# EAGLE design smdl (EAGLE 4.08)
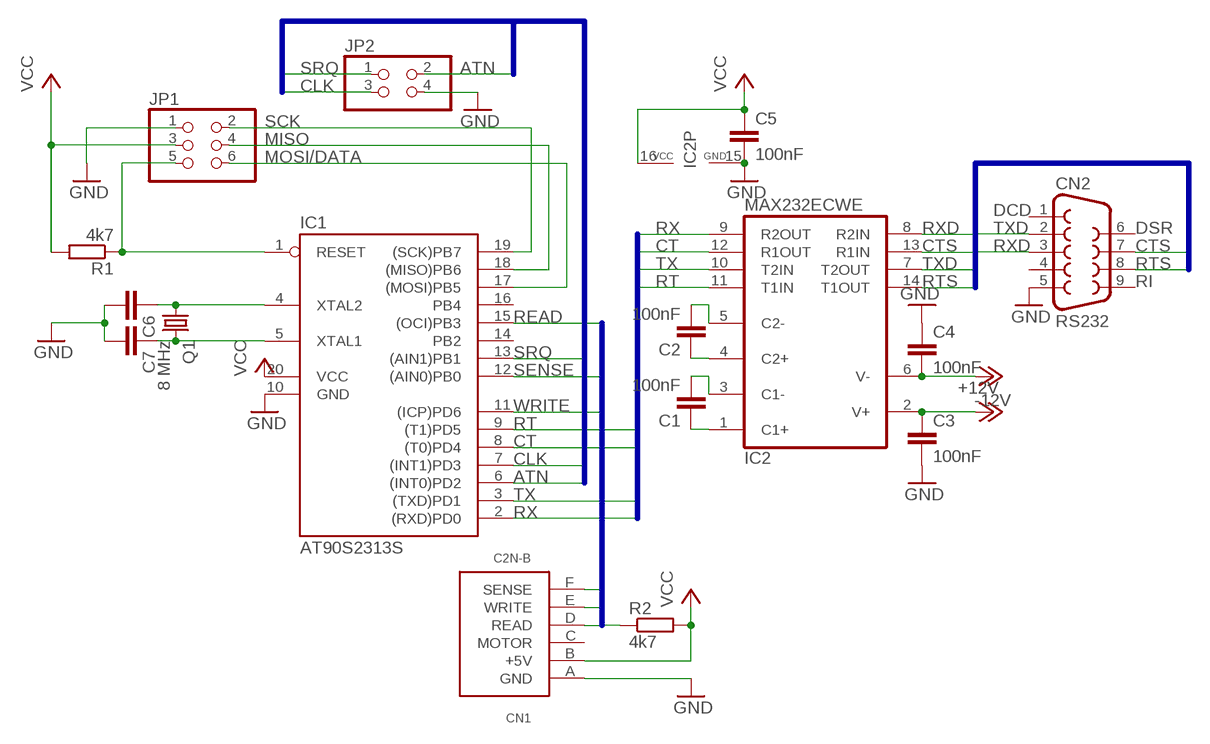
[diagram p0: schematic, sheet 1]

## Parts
C1  100nF  C-EUC0805  [C0805]
C2  100nF  C-EUC0805  [C0805]
C3  100nF  C-EUC0805  [C0805]
C4  100nF  C-EUC0805  [C0805]
C5  100nF  C-EUC0805  [C0805]
C6  C-EUC0603  [C0603]
C7  C-EUC0603  [C0603]
CN1  C2N-B  [C2N-B]
CN2  RS232  F09D  [F09D]
IC1  AT90S2313S  [SO-20L]
IC2  MAX232ECWE  [SO16L]
JP1  PINHD-2X3  [2X03]
JP2  PINHD-2X2  [2X02]
Q1  8 MHz  SM49  [SM49]
R1  4k7  R-EU_R0805  [R0805]
R2  4k7  R-EU_R0805  [R0805]

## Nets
+12V: C3.2 IC2.2(V+)
-12V: C4.1 IC2.6(V-)
ATN: IC1.6((INT0)PD2) JP2.2
C1+: C1.2 IC2.1(C1+)
C1-: C1.1 IC2.3(C1-)
C2+: C2.2 IC2.4(C2+)
C2-: C2.1 IC2.5(C2-)
CLK: IC1.7((INT1)PD3) JP2.3
CT: IC1.8((T0)PD4) IC2.12(R1OUT)
CTS: CN2.7 IC2.13(R1IN)
GND: C3.1 C4.2 C5.1 C6.1 C7.1 CN1.A(GND) CN2.5 IC1.10(GND) IC2.15(GND) JP1.1 JP2.4
MISO: IC1.18((MISO)PB6) JP1.4
MOSI/DATA: IC1.17((MOSI)PB5) JP1.6
READ: CN1.D(READ) IC1.15((OCI)PB3) R2.1
RESET: IC1.1(RESET) JP1.5 R1.1
RT: IC1.9((T1)PD5) IC2.11(T1IN)
RTS: CN2.8 IC2.14(T1OUT)
RX: IC1.2((RXD)PD0) IC2.9(R2OUT)
RXD: CN2.3 IC2.8(R2IN)
SCK: IC1.19((SCK)PB7) JP1.2
SENSE: CN1.F(SENSE) IC1.12((AIN0)PB0)
SRQ: IC1.13((AIN1)PB1) JP2.1
TX: IC1.3((TXD)PD1) IC2.10(T2IN)
TXD: CN2.2 IC2.7(T2OUT)
VCC: C5.2 CN1.B(+5V) IC1.20(VCC) IC2.16(VCC) JP1.3 R1.2 R2.2
WRITE: CN1.E(WRITE) IC1.11((ICP)PD6)
XTAL1: C7.2 IC1.5(XTAL1) Q1.2
XTAL2: C6.2 IC1.4(XTAL2) Q1.1
Unconnected: CN1.C(MOTOR) CN2.1 CN2.4 CN2.6 CN2.9 IC1.14(PB2) IC1.16(PB4)

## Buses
WRITE,READ,SENSE,MOTOR
DTR,CTS,RTS,RXD,TXD,DSR,RI,DCD
RX,TX,CT,RT
ATN,CLK,DATA,SRQ

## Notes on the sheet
- DCD
- DSR
- RI

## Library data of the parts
C1-C7 = rcl:C-EU: CAPACITOR, European symbol
CN1 = vic-20:C2N: Datassette connector
CN2 = con-subd:F09D: HARTING SUB-D
IC1 = atmel:AT90S2313: MICROCONTROLLER 2 Kbytes FLASH 128 bytes SRAM 128 bytes EEPROM UART
IC2 = maxim:MAX232ECWE: RS232 TRANSEIVER
JP1 = pinhead:PINHD-2X3: PIN HEADER
JP2 = pinhead:PINHD-2X2: PIN HEADER
Q1 = crystal:SM49: CRYSTAL
R1 R2 = rcl:R-EU_: RESISTOR, European symbol

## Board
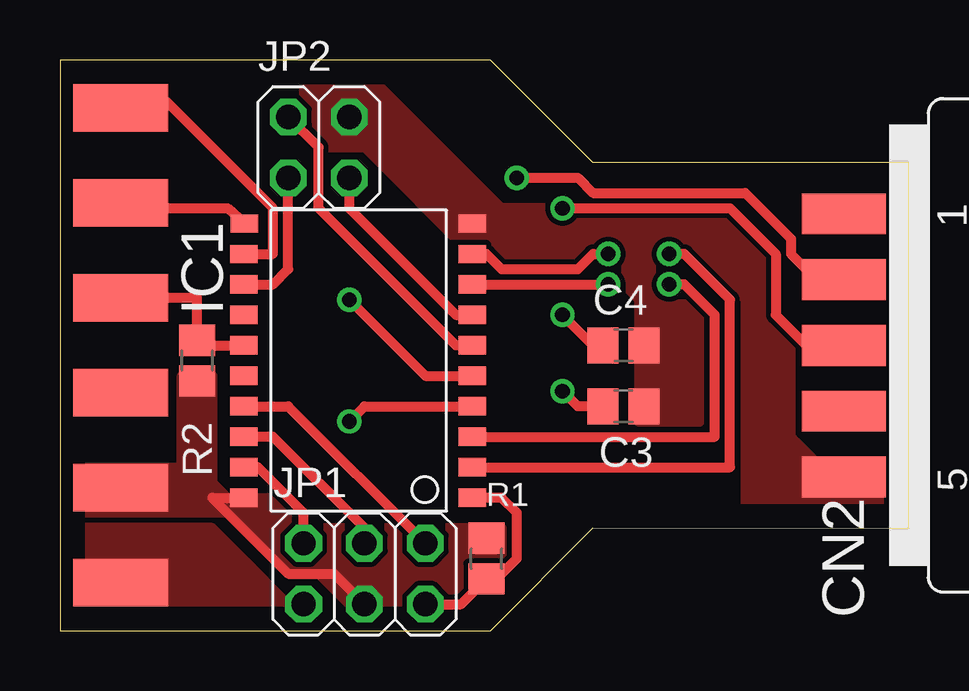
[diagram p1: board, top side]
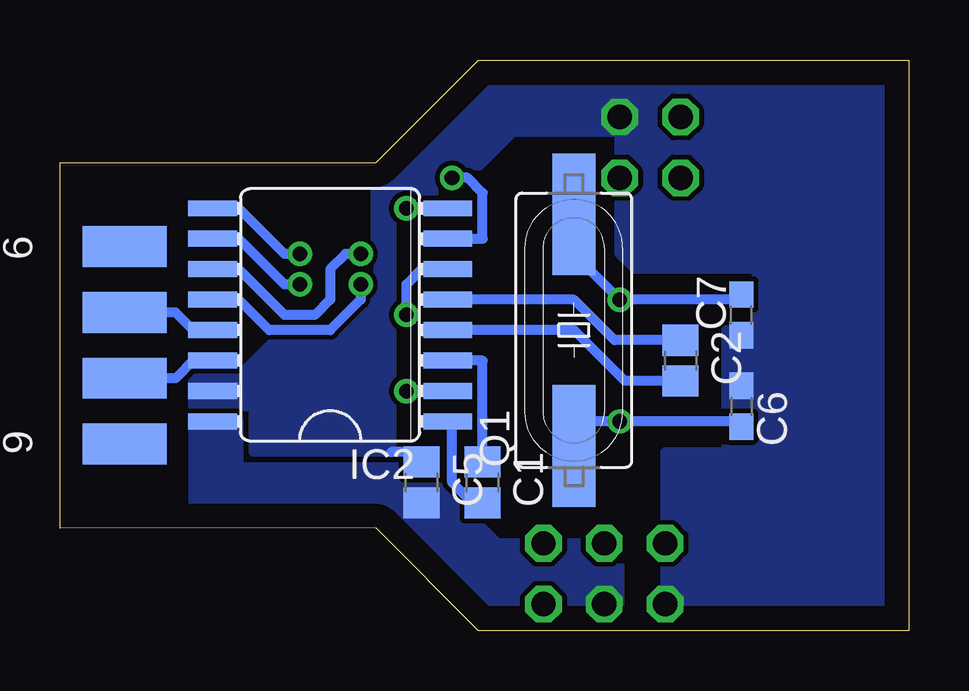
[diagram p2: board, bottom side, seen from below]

Size 35.39 x 23.8 mm. Coordinates in mm from the lower left corner, seen from the top.
Outline: 0,23.8 0,0 17.94,0 22.22,4.28 35.39,4.28 35.39,19.53 34.92,19.53 34.92,19.52 22.22,19.52 17.94,23.8 0,23.8
Copper layers used: Top, Bottom

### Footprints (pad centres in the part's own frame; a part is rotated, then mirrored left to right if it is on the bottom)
C0805 = smd 1.3 x 1.5: 1 -0.85,0; 2 0.85,0
C0603 = smd 1.1 x 1: 1 -0.85,0; 2 0.85,0
C2N-B = smd 1.98 x 3.96 bottom: A -9.9,0; B -5.94,0; C -1.98,0; D 1.98,0; E 5.94,0; F 9.9,0
F09D = smd 1.7 x 3.5: 1 -5.486,-6.045; 2 -2.743,-6.045; 3 0,-6.045; 4 2.743,-6.045; 5 5.486,-6.045 | smd 1.7 x 3.5 bottom: 6 -4.115,-6.045; 7 -1.372,-6.045; 8 1.372,-6.045; 9 4.115,-6.045
SO-20L = smd 0.762 x 1.143: 1 -5.08,-5.131; 2 -3.81,-5.131; 3 -2.54,-5.131; 4 -1.27,-5.131; 5 0,-5.131; 6 1.27,-5.131; 7 2.54,-5.131; 8 3.81,-5.131; 9 5.08,-5.131; 10 6.35,-5.131; 11 6.35,4.369; 12 5.08,4.394; 13 3.81,4.394; 14 2.54,4.394; 15 1.27,4.394; 16 0,4.394; 17 -1.27,4.394; 18 -2.54,4.394; 19 -3.81,4.394; 20 -5.08,4.394
SO16L = smd 0.66 x 2.032: 1 -4.445,-4.902; 2 -3.175,-4.902; 3 -1.905,-4.902; 4 -0.635,-4.902; 5 0.635,-4.902; 6 1.905,-4.902; 7 3.175,-4.902; 8 4.445,-4.902; 9 4.445,4.902; 10 3.175,4.902; 11 1.905,4.902; 12 0.635,4.902; 13 -0.635,4.902; 14 -1.905,4.902; 15 -3.175,4.902; 16 -4.445,4.902
2X03 = drill 1.016 octagon: 1 -2.54,-1.27; 2 -2.54,1.27; 3 0,-1.27; 4 0,1.27; 5 2.54,-1.27; 6 2.54,1.27
2X02 = drill 1.016 octagon: 1 -1.27,-1.27; 2 -1.27,1.27; 3 1.27,-1.27; 4 1.27,1.27
SM49 = smd 5.08 x 1.778: 1 -4.826,0; 2 4.826,0
R0805 = smd 1.3 x 1.5: 1 -0.85,0; 2 0.85,0

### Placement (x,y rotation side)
C1  17.78,6.18 270 bottom
C2  9.52,11.27 270 bottom
C3  23.49,9.36 180 top
C4  23.49,11.9 0 top
C5  20.32,6.18 270 bottom
C6  6.98,9.36 270 bottom
C7  6.98,13.17 90 bottom
CN1  2.54,11.9 90 bottom
CN2  38.73,11.9 270 top
IC1  12.06,10.63 90 top
IC2  24.12,13.17 90 bottom
JP1  12.69,2.38 0 top
JP2  10.79,20.16 0 top
Q1  13.96,12.54 90 bottom
R1  17.78,3.01 90 top
R2  5.71,11.27 270 top

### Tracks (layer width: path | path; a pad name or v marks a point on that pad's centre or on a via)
+12V  (via drill 0.61 pad 0.61)
  Top 0.406: v20.95,10 21.59,9.36 C3.2
  Bottom 0.406: v20.95,10 IC2.2
-12V  (via drill 0.61 pad 0.61)
  Top 0.406: C4.1 22.22,11.9 v20.95,13.17
  Bottom 0.406: IC2.6 20.32,15.08 20.95,14.44 v20.95,13.17
ATN
  Top 0.406: IC1.6 16.51,11.9 10.79,17.62 10.79,20.16 JP2.2
C1+
  Bottom 0.406: C1.2 18.2,5.33 19.05,6.18 19.05,8.73 IC2.1
C1-
  Bottom 0.406: C1.1 17.78,11.27 IC2.3
C2+
  Bottom 0.406: C2.2 11.84,10.42 13.96,12.54 IC2.4
C2-
  Bottom 0.406: C2.1 12.27,12.12 13.96,13.81 IC2.5
CLK
  Top 0.406: IC1.7 16.51,13.17 12.06,17.62 JP2.3
CT  (via drill 0.61 pad 0.61)
  Top 0.406: IC1.8 v22.86,14.44
  Bottom 0.406: v22.86,14.44 22.86,13.81 24.12,12.54 26.67,12.54 27.94,13.81 IC2.12
CTS
  Bottom 0.406: IC2.13 29.84,12.54 30.58,13.27 CN2.7
GND
  Bottom 0.406: C5.1 20.32,7.46 21.59,7.46
  pour Bottom (no thermals): -0.01,-0.17 10.15,-0.17 10.15,7.46 7.62,7.46 7.62,12.54 6.34,12.54 6.34,15.08 11.42,15.08 12.06,15.71 12.06,20.79 20.95,20.79 17.78,23.96 -0.01,23.96
  pour Top (no thermals): 24.12,8.73 26.67,8.73 26.67,13.17 25.39,14.44 25.39,16.35 26.03,16.35 28.57,13.81 28.57,4.28 34.28,4.28 34.28,6.82 31.75,6.82 30.48,8.09 30.48,11.9 29.84,12.54 29.84,15.08 27.3,17.62 24.12,17.62
  pour Top (no thermals): 24.12,17.62 18.41,17.62 12.69,23.33 10.15,23.33 10.15,20.16 12.69,20.16 17.14,15.71 22.22,15.71 24.12,13.81
  pour Bottom (no thermals): 27.3,7.46 27.3,9.36 29.84,9.36 29.84,10.63 27.94,10.63 22.22,16.35 22.22,19.52 18.41,23.33 16.51,23.33 16.51,20.79 19.05,18.25 20.95,18.25 21.59,17.62 21.59,7.46
  pour Top (no thermals): 10.79,-0.17 6.34,4.28 -0.01,4.28 -0.01,-0.17
MISO
  Top 0.406: IC1.18 8.88,8.09 12.69,4.28 JP1.4
MOSI/DATA
  Top 0.406: IC1.17 9.52,9.36 JP1.6
READ
  Top 0.406: 5.71,11.9 IC1.15 | R2.1 5.71,11.9 | CN1.D 5.71,13.88 5.71,11.9
RESET
  Top 0.406: IC1.1 18.41,5.55 19.05,4.92 19.05,3.01 18.2,2.16 R1.1 16.72,1.1 JP1.5
RT  (via drill 0.61 pad 0.61)
  Top 0.406: IC1.9 17.78,15.71 18.41,15.08 21.59,15.08 22.22,15.71 v22.86,15.71
  Bottom 0.406: v22.86,15.71 23.49,15.71 24.12,15.08 24.12,13.81 24.76,13.17 26.03,13.17 27.94,15.08 IC2.11
RTS
  Bottom 0.406: CN2.8 30.58,10.53 29.84,11.27 IC2.14
RX  (via drill 0.61 pad 0.61)
  Top 0.406: IC1.2 27.94,6.82 27.94,13.81 26.03,15.71 v25.39,15.71
  Bottom 0.406: v25.39,15.71 26.03,15.71 27.94,17.62 IC2.9 29.21,17.62
RXD  (via drill 0.61 pad 0.61)
  Top 0.406: v20.95,17.62 27.94,17.62 29.84,15.71 29.84,13.17 31.11,11.9 CN2.3
  Bottom 0.406: IC2.8 v20.95,17.62
SCK
  Top 0.406: IC1.19 8.25,6.82 10.15,4.92 JP1.2
SENSE
  Top 0.406: CN1.F 2.54,22.06 4.44,22.06 8.88,17.62 8.88,15.71 IC1.12
SRQ
  Top 0.406: IC1.13 8.88,14.44 9.52,15.08 JP2.1
TX  (via drill 0.61 pad 0.61)
  Top 0.406: IC1.3 27.3,8.09 27.3,13.17 26.03,14.44 v25.39,14.44
  Bottom 0.406: v25.39,14.44 26.03,14.44 27.94,16.35 IC2.10
TXD  (via drill 0.61 pad 0.61)
  Top 0.406: v19.05,18.89 21.59,18.89 22.22,18.25 28.57,18.25 30.48,16.35 30.48,15.71 31.54,14.64 CN2.2
  Bottom 0.406: v19.05,18.89 18.41,18.89 17.78,18.25 17.78,16.35 IC2.7
VCC
  Top 0.406: JP1.3 11.42,2.38 9.52,2.38 6.34,5.55 IC1.20
  Bottom 0.406: IC2.16 29.21,8.73
  pour Top (no thermals): 8.25,4.92 0.63,4.92 0.63,6.82 5.08,6.82 5.08,10.63 6.34,10.63 6.34,6.18 6.98,5.55 8.25,5.55
  pour Bottom (no thermals): 27.94,8.73 29.84,8.73 29.84,4.28 22.22,4.28 17.78,-0.17 12.06,-0.17 12.06,3.65 17.14,3.65 20.32,6.82 27.94,6.82
  pour Top (no thermals): 13.33,-0.17 10.79,2.38 9.52,2.38 6.34,5.55 8.88,5.55 10.15,4.28 18.41,4.28 18.41,-0.17
WRITE
  Top 0.406: CN1.E 2.54,17.62 6.98,17.62 IC1.11
XTAL1  (via drill 0.61)
  Top 0.406: IC1.5 15.23,10.63 v12.06,13.81
  Bottom 0.406: C7.2 6.98,13.81 v12.06,13.81 13.96,15.71 Q1.2
XTAL2  (via drill 0.61)
  Top 0.406: IC1.4 12.69,9.36 v12.06,8.73
  Bottom 0.406: C6.2 6.98,8.73 v12.06,8.73 13.96,8.73 Q1.1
